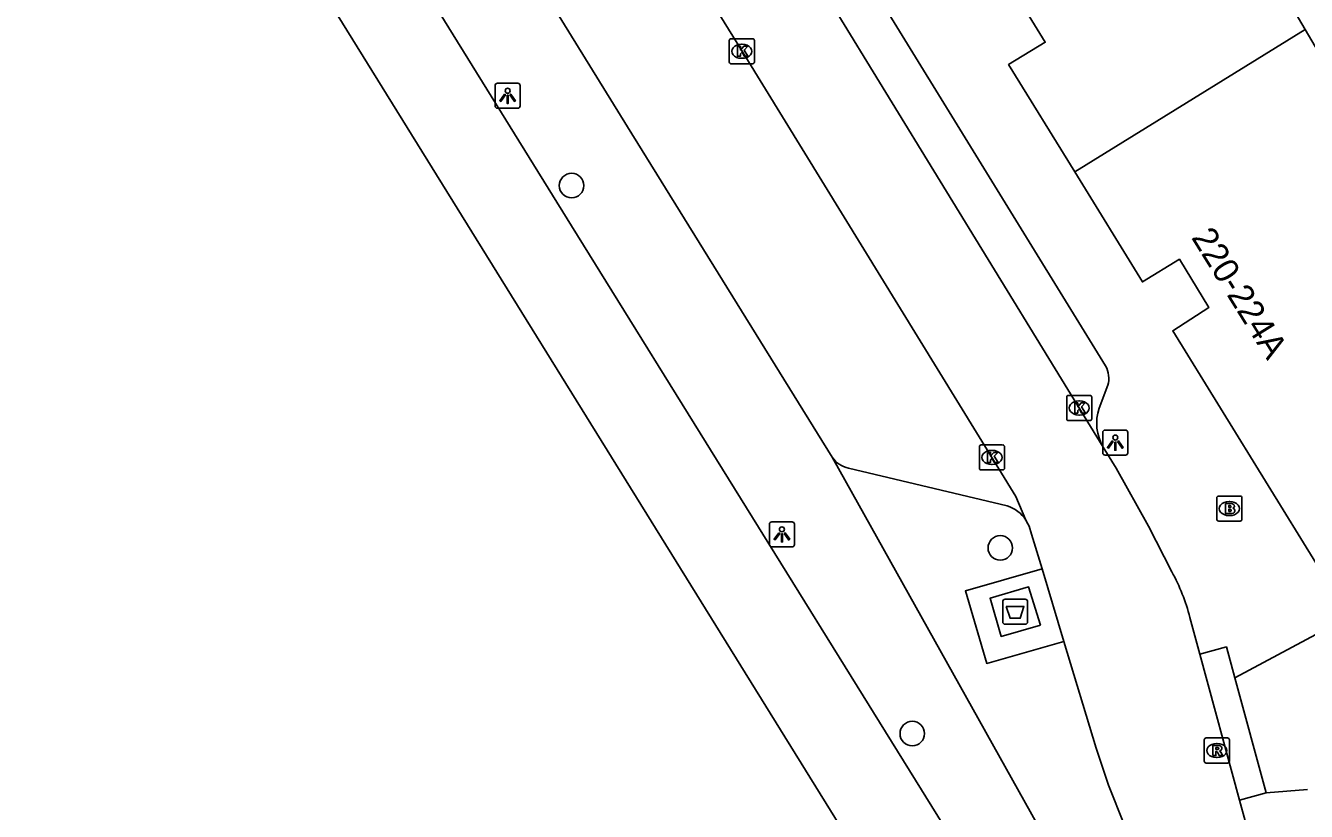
# Model space of a CAD drawing. Extents: x 160379 to 161131, y 383940 to 384849.
# Drawn here: x 160596.8 to 160647.9, y 384335.4 to 384366.7 of the extents above; entities that cross this region are included whole.
import ezdxf

# ---------------------------------------------------------------- set-up
doc = ezdxf.new("R2010")
doc.units = 0
for name, color, linetype in [('IMGEO_Afval_apart_plaats', 7, 'Continuous'), ('IMGEO_Boom', 7, 'Continuous'), ('IMGEO_Brandkraan', 7, 'Continuous'), ('IMGEO_Haag', 7, 'Continuous'), ('IMGEO_Kolk', 7, 'Continuous'), ('IMGEO_Lichtpunt', 7, 'Continuous'), ('IMGEO_Pand', 7, 'Continuous'), ('IMGEO_Pand_nummerreeks', 7, 'Continuous'), ('IMGEO_Parkeervlak_open', 7, 'Continuous'), ('IMGEO_Rijbaan_lokaal_gesloten', 7, 'Continuous'), ('IMGEO_Rijbaan_lokaal_open', 7, 'Continuous'), ('IMGEO_Rioolput', 7, 'Continuous'), ('IMGEO_Voetpad_gesloten', 7, 'Continuous'), ('IMGEO_Voetpad_open', 7, 'Continuous')]:
    doc.layers.add(name, color=color, linetype=linetype)

msp = doc.modelspace()

# ---------------------------------------------------------------- linework, layer by layer
at = {"layer": 'IMGEO_Afval_apart_plaats'}
for p, q in [((160635.871, 384343.835), (160636.661, 384343.835)), ((160636.661, 384343.835), (160635.871, 384343.835)), ((160635.771, 384342.935), (160635.771, 384343.735)), ((160635.771, 384343.735), (160635.771, 384342.935)), ((160636.761, 384343.735), (160636.761, 384342.935)), ((160636.761, 384342.935), (160636.761, 384343.735)), ((160636.661, 384342.835), (160635.871, 384342.835)), ((160635.871, 384342.835), (160636.661, 384342.835))]:
    msp.add_line(p, q, dxfattribs=at)
msp.add_lwpolyline([(160635.914, 384343.549), (160636.618, 384343.549), (160636.469, 384343.079), (160636.063, 384343.079), (160635.914, 384343.549)], dxfattribs=at)
for centre, start, end in [((160635.871, 384343.735), 90, 180), ((160635.871, 384343.735), 90, 180), ((160636.661, 384343.735), 0, 90), ((160636.661, 384343.735), 360, 90), ((160635.871, 384342.935), 180, 270), ((160635.871, 384342.935), 180, 270), ((160636.661, 384342.935), 270, 0), ((160636.661, 384342.935), 270, 0)]:
    msp.add_arc(centre, 0.1, start, end, dxfattribs=at)
at = {"layer": 'IMGEO_Boom'}
for centre in [(160618.59, 384360.305), (160635.676, 384345.878), (160632.169, 384338.484)]:
    msp.add_circle(centre, 0.489, dxfattribs=at)
at = {"layer": 'IMGEO_Brandkraan'}
for p, q in [((160644.304, 384347.017), (160644.304, 384347.869)), ((160644.379, 384347.943), (160645.231, 384347.943)), ((160645.305, 384347.869), (160645.305, 384347.017)), ((160644.792, 384347.723), (160644.817, 384347.723)), ((160645.231, 384346.943), (160644.379, 384346.943)), ((160644.815, 384347.163), (160644.79, 384347.163))]:
    msp.add_line(p, q, dxfattribs=at)
for points in [[(160644.304, 384347.017), (160644.304, 384347.869)], [(160644.379, 384347.943), (160645.231, 384347.943)], [(160645.305, 384347.869), (160645.305, 384347.017)], [(160644.652, 384347.643), (160644.652, 384347.243), (160644.865, 384347.243)], [(160644.883, 384347.643), (160644.652, 384347.643)], [(160644.831, 384347.562), (160644.777, 384347.562), (160644.777, 384347.486)], [(160644.777, 384347.486), (160644.83, 384347.486)], [(160644.839, 384347.41), (160644.777, 384347.41), (160644.777, 384347.329)], [(160644.777, 384347.329), (160644.839, 384347.329)], [(160645.231, 384346.943), (160644.379, 384346.943)]]:
    msp.add_lwpolyline(points, dxfattribs=at)
for centre, radius, start, end in [((160644.381, 384347.867), 0.0765, 91.552, 178.448), ((160644.381, 384347.867), 0.0765, 91.552, 178.448), ((160645.229, 384347.867), 0.0765, 1.552, 88.448), ((160645.229, 384347.867), 0.0765, 1.552, 88.448), ((160644.832, 384347.524), 0.0379, 267.8285, 90.9355), ((160644.84, 384347.369), 0.0404, 269.8759, 90.5077), ((160644.887, 384347.498), 0.145, 59.4692, 91.5367), ((160644.912, 384347.545), 0.0922, 285.5137, 58.1501), ((160644.917, 384347.353), 0.105, 301.3115, 78.989), ((160644.381, 384347.019), 0.0765, 181.552, 268.448), ((160644.381, 384347.019), 0.0765, 181.552, 268.448), ((160644.871, 384347.494), 0.251, 268.6676, 293.5347), ((160645.229, 384347.019), 0.0765, 271.552, 358.448), ((160645.229, 384347.019), 0.0765, 271.552, 358.448)]:
    msp.add_arc(centre, radius, start, end, dxfattribs=at)
for centre, major_axis, ratio, start_param, end_param in [((160644.791, 384347.443), (-0.387, 0.002), 0.722429, 4.712389, 7.853982), ((160644.816, 384347.443), (-0.39, 0.002), 0.717154, 1.570796, 4.712389)]:
    msp.add_ellipse(centre, major_axis=major_axis, ratio=ratio, start_param=start_param, end_param=end_param, dxfattribs=at)
at = {"layer": 'IMGEO_Haag'}
msp.add_lwpolyline([(160641.221, 384327.588), (160628.974, 384349.493)], dxfattribs=at)
at = {"layer": 'IMGEO_Kolk'}
for p, q in [((160624.876, 384365.226), (160624.876, 384366.078)), ((160624.951, 384366.152), (160625.803, 384366.152)), ((160625.364, 384365.932), (160625.389, 384365.932)), ((160625.877, 384366.078), (160625.877, 384365.226)), ((160625.387, 384365.372), (160625.362, 384365.372)), ((160625.803, 384365.152), (160624.951, 384365.152)), ((160638.396, 384351.948), (160639.248, 384351.948)), ((160638.321, 384351.022), (160638.321, 384351.874)), ((160638.809, 384351.728), (160638.834, 384351.728)), ((160639.322, 384351.874), (160639.322, 384351.022)), ((160639.248, 384350.948), (160638.396, 384350.948)), ((160638.832, 384351.168), (160638.807, 384351.168)), ((160634.843, 384349.054), (160634.843, 384349.906)), ((160634.918, 384349.98), (160635.77, 384349.98)), ((160635.844, 384349.906), (160635.844, 384349.054)), ((160635.331, 384349.76), (160635.356, 384349.76)), ((160635.77, 384348.98), (160634.918, 384348.98)), ((160635.354, 384349.2), (160635.329, 384349.2))]:
    msp.add_line(p, q, dxfattribs=at)
for points in [[(160624.876, 384365.226), (160624.876, 384366.078)], [(160624.951, 384366.152), (160625.803, 384366.152)], [(160625.197, 384365.852), (160625.32, 384365.852), (160625.32, 384365.701), (160625.45, 384365.852), (160625.614, 384365.852), (160625.468, 384365.701), (160625.621, 384365.452), (160625.469, 384365.452), (160625.384, 384365.616), (160625.32, 384365.549), (160625.32, 384365.452), (160625.197, 384365.452), (160625.197, 384365.852)], [(160625.877, 384366.078), (160625.877, 384365.226)], [(160625.803, 384365.152), (160624.951, 384365.152)], [(160638.396, 384351.948), (160639.248, 384351.948)], [(160638.321, 384351.022), (160638.321, 384351.874)], [(160638.642, 384351.648), (160638.765, 384351.648), (160638.765, 384351.497), (160638.895, 384351.648), (160639.059, 384351.648), (160638.913, 384351.497), (160639.066, 384351.248), (160638.914, 384351.248), (160638.829, 384351.412), (160638.765, 384351.345), (160638.765, 384351.248), (160638.642, 384351.248), (160638.642, 384351.648)], [(160639.322, 384351.874), (160639.322, 384351.022)], [(160639.248, 384350.948), (160638.396, 384350.948)], [(160634.843, 384349.054), (160634.843, 384349.906)], [(160634.918, 384349.98), (160635.77, 384349.98)], [(160635.844, 384349.906), (160635.844, 384349.054)], [(160635.164, 384349.68), (160635.287, 384349.68), (160635.287, 384349.529), (160635.417, 384349.68), (160635.581, 384349.68), (160635.435, 384349.529), (160635.588, 384349.28), (160635.436, 384349.28), (160635.351, 384349.444), (160635.287, 384349.377), (160635.287, 384349.28), (160635.164, 384349.28), (160635.164, 384349.68)], [(160635.77, 384348.98), (160634.918, 384348.98)]]:
    msp.add_lwpolyline(points, dxfattribs=at)
for centre, start, end in [((160624.953, 384366.076), 91.552, 178.448), ((160624.953, 384366.076), 91.552, 178.448), ((160625.801, 384366.076), 1.552, 88.448), ((160625.801, 384366.076), 1.552, 88.448), ((160624.953, 384365.228), 181.552, 268.448), ((160624.953, 384365.228), 181.552, 268.448), ((160625.801, 384365.228), 271.552, 358.448), ((160625.801, 384365.228), 271.552, 358.448), ((160638.398, 384351.872), 91.552, 178.448), ((160638.398, 384351.872), 91.552, 178.448), ((160639.246, 384351.872), 1.552, 88.448), ((160639.246, 384351.872), 1.552, 88.448), ((160638.398, 384351.024), 181.552, 268.448), ((160638.398, 384351.024), 181.552, 268.448), ((160639.246, 384351.024), 271.552, 358.448), ((160639.246, 384351.024), 271.552, 358.448), ((160634.92, 384349.904), 91.552, 178.448), ((160634.92, 384349.904), 91.552, 178.448), ((160635.768, 384349.904), 1.552, 88.448), ((160635.768, 384349.904), 1.552, 88.448), ((160634.92, 384349.056), 181.552, 268.448), ((160634.92, 384349.056), 181.552, 268.448), ((160635.768, 384349.056), 271.552, 358.448), ((160635.768, 384349.056), 271.552, 358.448)]:
    msp.add_arc(centre, 0.0765, start, end, dxfattribs=at)
for centre, major_axis, ratio, start_param, end_param in [((160625.363, 384365.652), (-0.387, 0.002), 0.722429, 4.712389, 7.853982), ((160625.388, 384365.652), (-0.39, 0.002), 0.717154, 1.570796, 4.712389), ((160638.808, 384351.448), (-0.387, 0.002), 0.722429, 4.712389, 7.853982), ((160638.833, 384351.448), (-0.39, 0.002), 0.717154, 1.570796, 4.712389), ((160635.33, 384349.48), (-0.387, 0.002), 0.722429, 4.712389, 7.853982), ((160635.355, 384349.48), (-0.39, 0.002), 0.717154, 1.570796, 4.712389)]:
    msp.add_ellipse(centre, major_axis=major_axis, ratio=ratio, start_param=start_param, end_param=end_param, dxfattribs=at)
at = {"layer": 'IMGEO_Lichtpunt'}
for p, q in [((160615.544, 384364.283), (160615.544, 384363.476)), ((160615.544, 384364.283), (160615.544, 384363.476)), ((160616.446, 384364.378), (160615.638, 384364.378)), ((160616.446, 384364.378), (160615.638, 384364.378)), ((160616.54, 384363.476), (160616.54, 384364.283)), ((160616.54, 384363.476), (160616.54, 384364.283)), ((160615.638, 384363.382), (160616.446, 384363.382)), ((160615.638, 384363.382), (160616.446, 384363.382)), ((160639.76, 384350.473), (160639.76, 384349.666)), ((160639.76, 384350.473), (160639.76, 384349.666)), ((160640.662, 384350.568), (160639.854, 384350.568)), ((160640.662, 384350.568), (160639.854, 384350.568)), ((160640.756, 384349.666), (160640.756, 384350.473)), ((160640.756, 384349.666), (160640.756, 384350.473)), ((160639.854, 384349.572), (160640.662, 384349.572)), ((160639.854, 384349.572), (160640.662, 384349.572)), ((160626.475, 384346.819), (160626.475, 384346.012)), ((160626.475, 384346.819), (160626.475, 384346.012)), ((160627.377, 384346.914), (160626.569, 384346.914)), ((160627.377, 384346.914), (160626.569, 384346.914)), ((160627.471, 384346.012), (160627.471, 384346.819)), ((160627.471, 384346.012), (160627.471, 384346.819)), ((160626.569, 384345.918), (160627.377, 384345.918)), ((160626.569, 384345.918), (160627.377, 384345.918))]:
    msp.add_line(p, q, dxfattribs=at)
for points in [[(160615.918, 384363.947), (160615.957, 384363.919), (160615.769, 384363.657), (160615.731, 384363.684), (160615.918, 384363.947)], [(160616.02, 384363.899), (160616.067, 384363.899), (160616.067, 384363.577), (160616.02, 384363.577), (160616.02, 384363.899)], [(160616.13, 384363.919), (160616.168, 384363.946), (160616.355, 384363.684), (160616.316, 384363.656), (160616.13, 384363.919)], [(160640.134, 384350.137), (160640.173, 384350.109), (160639.985, 384349.847), (160639.947, 384349.874), (160640.134, 384350.137)], [(160640.236, 384350.089), (160640.283, 384350.089), (160640.283, 384349.767), (160640.236, 384349.767), (160640.236, 384350.089)], [(160640.346, 384350.109), (160640.384, 384350.136), (160640.571, 384349.874), (160640.532, 384349.846), (160640.346, 384350.109)], [(160626.849, 384346.483), (160626.888, 384346.455), (160626.7, 384346.193), (160626.662, 384346.22), (160626.849, 384346.483)], [(160626.951, 384346.435), (160626.998, 384346.435), (160626.998, 384346.113), (160626.951, 384346.113), (160626.951, 384346.435)], [(160627.061, 384346.455), (160627.099, 384346.482), (160627.286, 384346.22), (160627.247, 384346.192), (160627.061, 384346.455)]]:
    msp.add_lwpolyline(points, dxfattribs=at)
for centre in [(160616.043, 384364.081), (160640.259, 384350.271), (160626.974, 384346.617)]:
    msp.add_circle(centre, 0.0994, dxfattribs=at)
for centre, start, end in [((160615.638, 384364.283), 90, 180), ((160615.638, 384364.283), 90, 180), ((160616.446, 384364.283), 0, 90), ((160616.446, 384364.283), 0, 90), ((160615.638, 384363.476), 180, 270), ((160615.638, 384363.476), 180, 270), ((160616.446, 384363.476), 270, 0), ((160616.446, 384363.476), 270, 360), ((160639.854, 384350.473), 90, 180), ((160639.854, 384350.473), 90, 180), ((160640.662, 384350.473), 0, 90), ((160640.662, 384350.473), 0, 90), ((160639.854, 384349.666), 180, 270), ((160639.854, 384349.666), 180, 270), ((160640.662, 384349.666), 270, 0), ((160640.662, 384349.666), 270, 360), ((160626.569, 384346.819), 90, 180), ((160626.569, 384346.819), 90, 180), ((160627.377, 384346.819), 0, 90), ((160627.377, 384346.819), 0, 90), ((160626.569, 384346.012), 180, 270), ((160626.569, 384346.012), 180, 270), ((160627.377, 384346.012), 270, 0), ((160627.377, 384346.012), 270, 360)]:
    msp.add_arc(centre, 0.0946, start, end, dxfattribs=at)
at = {"layer": 'IMGEO_Pand'}
for points in [[(160647.827, 384366.514), (160645.708, 384370.122), (160640.874, 384378.352), (160638.874, 384377.118), (160636.514, 384380.871)], [(160629.108, 384376.319), (160634.786, 384367.095), (160636.256, 384367.993), (160637.465, 384366.015), (160636.009, 384365.125), (160638.642, 384360.849)], [(160638.642, 384360.849), (160647.827, 384366.514)], [(160652.673, 384358.264), (160650.135, 384362.585), (160647.827, 384366.514)], [(160638.642, 384360.849), (160641.337, 384356.471), (160642.816, 384357.374), (160643.989, 384355.452), (160642.55, 384354.521), (160648.252, 384345.283)]]:
    msp.add_lwpolyline(points, dxfattribs=at)
at = {"layer": 'IMGEO_Parkeervlak_open'}
for points in [[(160628.974, 384349.493), (160620.816, 384362.648), (160596.919, 384401.325)], [(160635.947, 384347.555), (160629.625, 384349.05)]]:
    msp.add_lwpolyline(points, dxfattribs=at)
for centre, radius, start, end in [((160629.862, 384350.098), 1.074, 214.2636, 257.2665), ((160635.493, 384346.18), 1.448, 33.8245, 71.7291)]:
    msp.add_arc(centre, radius, start, end, dxfattribs=at)
at = {"layer": 'IMGEO_Rijbaan_lokaal_gesloten'}
for points in [[(160635.054, 384325.513), (160590.004, 384398.14), (160582.508, 384410.224), (160574.505, 384423.164), (160548.855, 384464.222)], [(160558.242, 384455.966), (160562.533, 384449.098), (160618.594, 384358.706), (160638.069, 384327.324)]]:
    msp.add_lwpolyline(points, dxfattribs=at)
at = {"layer": 'IMGEO_Rijbaan_lokaal_open'}
for points in [[(160639.777, 384349.891), (160628.948, 384367.536), (160604.906, 384406.482)], [(160601.021, 384404.979), (160625.537, 384365.419), (160636.3, 384347.93), (160636.696, 384346.986)], [(160639.777, 384349.891), (160640.29, 384349.049), (160641.583, 384346.737), (160642.51, 384344.924)], [(160637.34, 384345.044), (160636.922, 384346.426), (160636.829, 384346.74), (160636.776, 384346.837), (160636.696, 384346.986)], [(160637.34, 384345.044), (160638.213, 384342.157)], [(160643.229, 384343.109), (160643.626, 384341.648)], [(160640.616, 384334.859), (160639.988, 384336.436), (160639.501, 384337.897), (160638.213, 384342.157)], [(160643.626, 384341.648), (160645.204, 384335.839)], [(160645.204, 384335.839), (160645.654, 384334.183)]]:
    msp.add_lwpolyline(points, dxfattribs=at)
msp.add_arc((160635.976, 384341.286), 7.479, 14.1113, 29.1101, dxfattribs=at)
at = {"layer": 'IMGEO_Rioolput'}
for p, q in [((160643.806, 384337.383), (160643.806, 384338.235)), ((160643.881, 384338.309), (160644.733, 384338.309)), ((160644.807, 384338.235), (160644.807, 384337.383)), ((160644.294, 384338.089), (160644.319, 384338.089)), ((160644.733, 384337.309), (160643.881, 384337.309)), ((160644.317, 384337.529), (160644.292, 384337.529))]:
    msp.add_line(p, q, dxfattribs=at)
for points in [[(160643.806, 384337.383), (160643.806, 384338.235)], [(160643.881, 384338.309), (160644.733, 384338.309)], [(160644.807, 384338.235), (160644.807, 384337.383)], [(160644.395, 384338.007), (160644.143, 384338.009), (160644.143, 384337.609)], [(160644.143, 384337.609), (160644.267, 384337.609), (160644.267, 384337.771), (160644.278, 384337.771)], [(160644.321, 384337.928), (160644.267, 384337.928), (160644.267, 384337.847)], [(160644.267, 384337.847), (160644.319, 384337.847)], [(160644.325, 384337.742), (160644.396, 384337.609), (160644.536, 384337.609), (160644.471, 384337.735)], [(160644.733, 384337.309), (160643.881, 384337.309)]]:
    msp.add_lwpolyline(points, dxfattribs=at)
for centre, radius, start, end in [((160643.883, 384338.233), 0.0765, 91.552, 178.448), ((160643.883, 384338.233), 0.0765, 91.552, 178.448), ((160644.731, 384338.233), 0.0765, 1.552, 88.448), ((160644.731, 384338.233), 0.0765, 1.552, 88.448), ((160644.277, 384337.718), 0.0533, 26.0293, 88.6989), ((160644.303, 384338.036), 0.19, 274.7715, 282.9687), ((160644.327, 384337.832), 0.0964, 77.0061, 93.1865), ((160644.341, 384337.889), 0.0378, 276.6634, 79.6772), ((160644.394, 384337.897), 0.109, 350.3612, 89.416), ((160644.392, 384337.897), 0.112, 277.5842, 350.9817), ((160644.376, 384337.682), 0.108, 29.5134, 73.7905), ((160643.883, 384337.385), 0.0765, 181.552, 268.448), ((160643.883, 384337.385), 0.0765, 181.552, 268.448), ((160644.731, 384337.385), 0.0765, 271.552, 358.448), ((160644.731, 384337.385), 0.0765, 271.552, 358.448)]:
    msp.add_arc(centre, radius, start, end, dxfattribs=at)
for centre, major_axis, ratio, start_param, end_param in [((160644.293, 384337.809), (-0.387, 0.002), 0.722429, 4.712389, 7.853982), ((160644.318, 384337.809), (-0.39, 0.002), 0.717154, 1.570796, 4.712389)]:
    msp.add_ellipse(centre, major_axis=major_axis, ratio=ratio, start_param=start_param, end_param=end_param, dxfattribs=at)
at = {"layer": 'IMGEO_Voetpad_gesloten'}
msp.add_lwpolyline([(160637.272, 384342.795), (160636.805, 384344.325), (160635.268, 384343.875), (160635.711, 384342.351), (160637.272, 384342.795)], dxfattribs=at)
at = {"layer": 'IMGEO_Voetpad_open'}
for points in [[(160626.626, 384374.614), (160628.611, 384371.407), (160630.486, 384368.367), (160639.872, 384353.122)], [(160639.959, 384352.352), (160639.617, 384351.441)], [(160638.213, 384342.157), (160635.133, 384341.279), (160634.284, 384344.162), (160637.34, 384345.044)], [(160645.022, 384340.708), (160649.594, 384343.146)], [(160643.626, 384341.648), (160644.688, 384341.937), (160645.022, 384340.708)], [(160646.267, 384336.128), (160645.022, 384340.708)], [(160646.267, 384336.128), (160645.204, 384335.839)], [(160647.92, 384336.252), (160646.267, 384336.128)]]:
    msp.add_lwpolyline(points, dxfattribs=at)
for centre, radius, start, end in [((160639.011, 384352.635), 0.989, 343.3933, 29.4993), ((160641.378, 384350.84), 1.861, 161.1427, 210.6444)]:
    msp.add_arc(centre, radius, start, end, dxfattribs=at)

# ---------------------------------------------------------------- texts
at = {"layer": 'IMGEO_Pand_nummerreeks'}
msp.add_text('220-224A', height=1, rotation=301.8562, dxfattribs=at).set_placement((160643.267, 384358.237))

doc.saveas('drawing.dxf')
